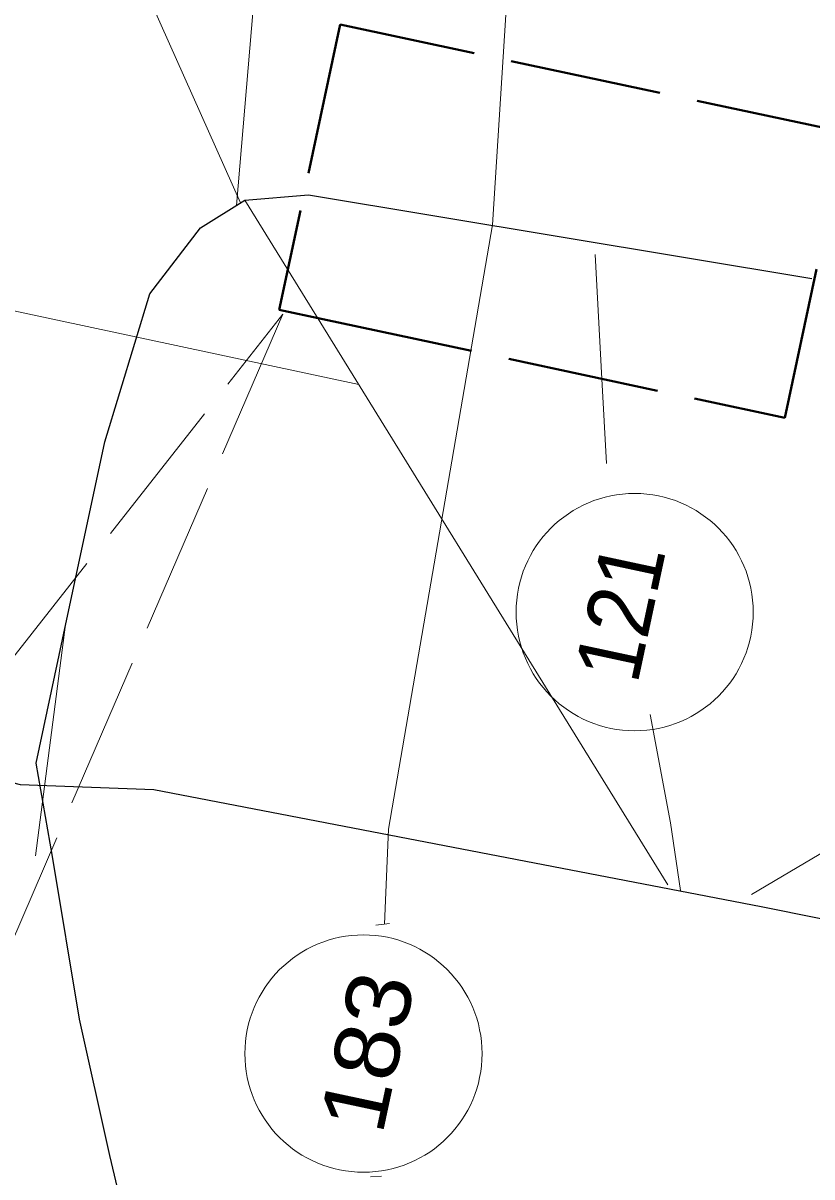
# Model space of a CAD drawing. Extents: x 2363411 to 2369126, y 6976878 to 6988319.
# Drawn here: x 2365907 to 2365969.3, y 6977102.1 to 6977193.1 of the extents above; entities that cross this region are included whole.
import ezdxf

# ---------------------------------------------------------------- set-up
doc = ezdxf.new("R2010")
doc.units = 0
doc.header["$LTSCALE"] = 2
doc.linetypes.add('LONG_DASHED', pattern=[7.5, 6, -1.5])
doc.layers.add('62', color=7, linetype='Continuous', lineweight=13)
doc.layers.add('63', color=7, linetype='Continuous', lineweight=13)

msp = doc.modelspace()

# ---------------------------------------------------------------- linework, layer by layer
at = {"layer": '62', "lineweight": 25}
for p, q in [((2365924.542, 6977179.148), (2365929.577, 6977179.568)), ((2365929.577, 6977179.567), (2365969.309, 6977172.965))]:
    msp.add_line(p, q, dxfattribs=at)
at = {"layer": '62'}
for p, q in [((2365924.542, 6977179.148), (2365957.937, 6977125.14)), ((2365952.734, 6977165.049), (2365952.202, 6977174.848)), ((2365933.536, 6977164.594), (2365890.648, 6977173.758)), ((2365953.097, 6977158.367), (2365952.734, 6977165.049)), ((2365908.01, 6977127.409), (2365910.37, 6977145.66)), ((2365958.131, 6977130.025), (2365956.532, 6977138.578)), ((2365958.131, 6977130.025), (2365958.943, 6977124.674)), ((2365934.891, 6977121.941), (2365935.957, 6977122.081)), ((2365934.446, 6977102.09), (2365935.329, 6977102.13))]:
    msp.add_line(p, q, dxfattribs=at)
for points in [[(2365923.878, 6977178.738), (2365925.447, 6977197.384), (2365927.159, 6977214.876)], [(2365911.612, 6977205.657), (2365916.624, 6977195.931), (2365924.198, 6977178.946)], [(2365945.46, 6977198.769), (2365944.099, 6977177.201), (2365935.888, 6977129.508), (2365935.556, 6977122.03)], [(2366015.745, 6977154.231), (2365993.954, 6977141.745), (2365964.537, 6977124.352)]]:
    msp.add_lwpolyline(points, dxfattribs=at)
at = {"layer": '62', "linetype": 'LONG_DASHED', "lineweight": 40}
msp.add_lwpolyline([(2365930.702, 6977169.756), (2365967.165, 6977161.965), (2365971.977, 6977184.476), (2365932.06, 6977193.005), (2365927.248, 6977170.494)], close=True, dxfattribs=at)
at = {"layer": '62', "lineweight": 25}
for points in [[(2365922.442, 6977067.124), (2365918.148, 6977078.257), (2365916.442, 6977093.003), (2365913.887, 6977103.765), (2365911.492, 6977114.516), (2365909.362, 6977127.375), (2365908.054, 6977134.719), (2365910.142, 6977144.49), (2365913.476, 6977160.09), (2365917.048, 6977171.753), (2365921.041, 6977176.974), (2365924.542, 6977179.148)], [(2365863.073, 6977144.33), (2365906.797, 6977133.032), (2365917.348, 6977132.661)], [(2365917.348, 6977132.661), (2365965.303, 6977123.405), (2366019.993, 6977112.413), (2366090.955, 6977103.692), (2366125.134, 6977113.209)]]:
    msp.add_lwpolyline(points, dxfattribs=at)
at = {"layer": '62', "linetype": 'LONG_DASHED'}
for points in [[(2365886.099, 6977117.482), (2365927.543, 6977170.155), (2365903.1, 6977113.573)], [(2365886.099, 6977117.482), (2365927.543, 6977170.155), (2365903.1, 6977113.573), (2365886.099, 6977117.482)]]:
    msp.add_lwpolyline(points, close=True, dxfattribs=at)
at = {"layer": '62'}
for centre in [(2365955.314, 6977146.643), (2365933.903, 6977111.813)]:
    msp.add_circle(centre, 9.364, dxfattribs=at)
at = {"layer": '63', "lineweight": 25}
for p, q in [((2365924.542, 6977179.148), (2365929.577, 6977179.568)), ((2365929.577, 6977179.567), (2365969.309, 6977172.965))]:
    msp.add_line(p, q, dxfattribs=at)
at = {"layer": '63'}
for p, q in [((2365924.542, 6977179.148), (2365957.937, 6977125.14)), ((2365952.734, 6977165.049), (2365952.202, 6977174.848)), ((2365933.536, 6977164.594), (2365890.648, 6977173.758)), ((2365953.097, 6977158.367), (2365952.734, 6977165.049)), ((2365908.01, 6977127.409), (2365910.37, 6977145.66)), ((2365958.131, 6977130.025), (2365956.532, 6977138.578)), ((2365958.131, 6977130.025), (2365958.943, 6977124.674)), ((2365934.891, 6977121.941), (2365935.957, 6977122.081)), ((2365934.446, 6977102.09), (2365935.329, 6977102.13))]:
    msp.add_line(p, q, dxfattribs=at)
for points in [[(2365923.878, 6977178.738), (2365925.447, 6977197.384), (2365927.159, 6977214.876)], [(2365911.612, 6977205.657), (2365916.624, 6977195.931), (2365924.198, 6977178.946)], [(2365945.46, 6977198.769), (2365944.099, 6977177.201), (2365935.888, 6977129.508), (2365935.556, 6977122.03)], [(2366015.745, 6977154.231), (2365993.954, 6977141.745), (2365964.537, 6977124.352)]]:
    msp.add_lwpolyline(points, dxfattribs=at)
at = {"layer": '63', "linetype": 'LONG_DASHED', "lineweight": 40}
msp.add_lwpolyline([(2365930.702, 6977169.756), (2365967.165, 6977161.965), (2365971.977, 6977184.476), (2365932.06, 6977193.005), (2365927.248, 6977170.494)], close=True, dxfattribs=at)
at = {"layer": '63', "lineweight": 25}
for points in [[(2365922.442, 6977067.124), (2365918.148, 6977078.257), (2365916.442, 6977093.003), (2365913.887, 6977103.765), (2365911.492, 6977114.516), (2365909.362, 6977127.375), (2365908.054, 6977134.719), (2365910.142, 6977144.49), (2365913.476, 6977160.09), (2365917.048, 6977171.753), (2365921.041, 6977176.974), (2365924.542, 6977179.148)], [(2365863.073, 6977144.33), (2365906.797, 6977133.032), (2365917.348, 6977132.661)], [(2365917.348, 6977132.661), (2365965.303, 6977123.405), (2366019.993, 6977112.413), (2366090.955, 6977103.692), (2366125.134, 6977113.209)]]:
    msp.add_lwpolyline(points, dxfattribs=at)
at = {"layer": '63', "linetype": 'LONG_DASHED'}
for points in [[(2365886.099, 6977117.482), (2365927.543, 6977170.155), (2365903.1, 6977113.573)], [(2365886.099, 6977117.482), (2365927.543, 6977170.155), (2365903.1, 6977113.573), (2365886.099, 6977117.482)]]:
    msp.add_lwpolyline(points, close=True, dxfattribs=at)
at = {"layer": '63'}
for centre in [(2365955.314, 6977146.643), (2365933.903, 6977111.813)]:
    msp.add_circle(centre, 9.364, dxfattribs=at)

# ---------------------------------------------------------------- texts
at = {"layer": '62'}
for s, width, p in [('121', 0.95, (2365955.524, 6977140.868)), ('183', 1.1, (2365935.384, 6977105.295))]:
    msp.add_text(s, height=5.099, rotation=77.939, dxfattribs=dict(at, width=width)).set_placement(p)
at = {"layer": '63'}
for s, width, p in [('121', 0.95, (2365955.524, 6977140.868)), ('183', 1.1, (2365935.384, 6977105.295))]:
    msp.add_text(s, height=5.099, rotation=77.939, dxfattribs=dict(at, width=width)).set_placement(p)

doc.saveas('drawing.dxf')
